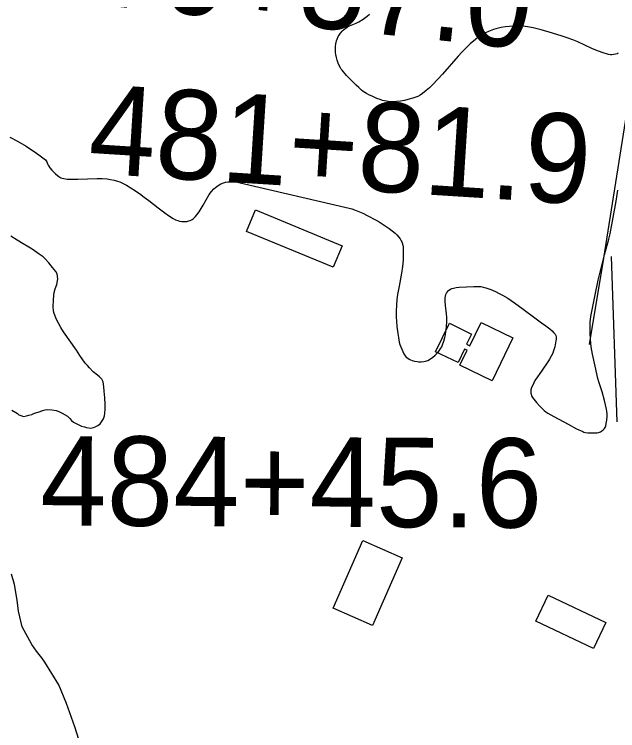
# Model space of a CAD drawing. Extents: x 3161615 to 3199515, y 867541 to 892976.
# Drawn here: x 3176440 to 3177115, y 880727 to 881529 of the extents above; entities that cross this region are included whole.
import ezdxf

# ---------------------------------------------------------------- set-up
doc = ezdxf.new("R2010")
doc.units = 0
for name, color, linetype in [('V-BLDG-OTLN', 7, 'Continuous'), ('V-SITE-VEGE', 7, 'Continuous'), ('V-SURV-IDEN', 7, 'Continuous'), ('V-TOPO-SHOR', 7, 'Continuous')]:
    doc.layers.add(name, color=color, linetype=linetype)

msp = doc.modelspace()

# ---------------------------------------------------------------- linework, layer by layer
at = {"layer": 'V-BLDG-OTLN'}
for points in [[(3176709.39, 881309.68), (3176806.32, 881269.65), (3176796.36, 881245.54), (3176699.43, 881285.56)], [(3176974.18, 881118.57), (3176938.19, 881136.05), (3176946.24, 881152.63), (3176943.37, 881154.03), (3176935.99, 881138.84), (3176910.95, 881151.01), (3176926.39, 881182.79), (3176951.12, 881170.77), (3176945.62, 881159.45), (3176949.1, 881157.76), (3176961.72, 881183.73), (3176997.41, 881166.4)], [(3176796.44, 880864.16), (3176829.6, 880939.81), (3176873.59, 880920.53), (3176840.43, 880844.87)], [(3177022.88, 880849.66), (3177036.62, 880878.78), (3177101.37, 880848.23), (3177087.63, 880819.11)]]:
    msp.add_lwpolyline(points, close=True, dxfattribs=at)
at = {"layer": 'V-SITE-VEGE'}
for p, q in [((3176825.15, 881520.24), (3176829.77, 881523.17)), ((3176829.77, 881523.17), (3176834.24, 881526.3)), ((3176834.24, 881526.3), (3176837.12, 881528.54)), ((3176812.12, 881514.2), (3176814.51, 881515.5)), ((3176814.51, 881515.5), (3176821.96, 881518.6)), ((3176821.96, 881518.6), (3176825.15, 881520.24)), ((3176988.92, 881514.53), (3176984.22, 881513.8)), ((3176993.63, 881514.98), (3176988.92, 881514.53)), ((3177002.49, 881515.43), (3176993.63, 881514.98)), ((3177008.19, 881515.32), (3177002.49, 881515.43)), ((3177011.03, 881515.08), (3177008.19, 881515.32)), ((3177013.85, 881514.68), (3177011.03, 881515.08)), ((3177019.95, 881513.49), (3177013.85, 881514.68)), ((3176802.94, 881505.16), (3176804.57, 881507.52)), ((3176804.57, 881507.52), (3176806.36, 881509.6)), ((3176806.36, 881509.6), (3176807.64, 881510.85)), ((3176807.64, 881510.85), (3176809.46, 881512.37)), ((3176809.46, 881512.37), (3176812.12, 881514.2)), ((3176966.73, 881507.75), (3176962.27, 881505.26)), ((3176970.23, 881509.41), (3176966.73, 881507.75)), ((3176975.57, 881511.5), (3176970.23, 881509.41)), ((3176978.3, 881512.38), (3176975.57, 881511.5)), ((3176981.1, 881513.12), (3176978.3, 881512.38)), ((3176984.22, 881513.8), (3176981.1, 881513.12)), ((3177028.98, 881511.28), (3177019.95, 881513.49)), ((3177037.93, 881508.7), (3177028.98, 881511.28)), ((3177051.33, 881504.54), (3177037.93, 881508.7)), ((3176799.48, 881495.64), (3176800.17, 881498.8)), ((3176800.17, 881498.8), (3176800.84, 881500.88)), ((3176800.84, 881500.88), (3176802.06, 881503.61)), ((3176802.06, 881503.61), (3176802.94, 881505.16)), ((3176955.38, 881500.38), (3176949.64, 881495.51)), ((3176958.07, 881502.44), (3176955.38, 881500.38)), ((3176962.27, 881505.26), (3176958.07, 881502.44)), ((3177057.95, 881502.31), (3177051.33, 881504.54)), ((3177064.52, 881499.88), (3177057.95, 881502.31)), ((3177069.85, 881497.62), (3177064.52, 881499.88)), ((3176798.99, 881488.61), (3176799.12, 881492.45)), ((3176799.12, 881492.45), (3176799.48, 881495.64)), ((3176949.64, 881495.51), (3176944.19, 881490.33)), ((3177085.6, 881490.22), (3177069.85, 881497.62)), ((3176799.11, 881485.71), (3176798.99, 881488.61)), ((3176799.33, 881483.54), (3176799.11, 881485.71)), ((3176799.91, 881480.28), (3176799.33, 881483.54)), ((3176940.7, 881486.74), (3176936.17, 881481.84)), ((3176944.19, 881490.33), (3176940.7, 881486.74)), ((3177090.21, 881488.32), (3177085.6, 881490.22)), ((3177097.23, 881485.76), (3177090.21, 881488.32)), ((3177104.33, 881483.56), (3177097.23, 881485.76)), ((3177106.33, 881483.23), (3177104.33, 881483.56)), ((3177107.87, 881483.23), (3177106.33, 881483.23)), ((3177110.2, 881483.49), (3177107.87, 881483.23)), ((3177113.9, 881484.24), (3177110.2, 881483.49)), ((3177114.52, 881484.56), (3177113.9, 881484.24)), ((3177115.02, 881485.09), (3177114.52, 881484.56)), ((3176800.81, 881477.08), (3176799.91, 881480.28)), ((3176801.91, 881474.07), (3176800.81, 881477.08)), ((3176936.17, 881481.84), (3176918.61, 881461.63)), ((3176802.83, 881471.9), (3176801.91, 881474.07)), ((3176804.47, 881468.79), (3176802.83, 881471.9)), ((3176805.43, 881467.31), (3176804.47, 881468.79)), ((3176806.51, 881465.89), (3176805.43, 881467.31)), ((3176811.43, 881460.25), (3176806.51, 881465.89)), ((3176816.56, 881454.87), (3176811.43, 881460.25)), ((3176918.61, 881461.63), (3176913.47, 881455.95)), ((3176822.19, 881449.24), (3176816.56, 881454.87)), ((3176913.47, 881455.95), (3176907.38, 881449.69)), ((3176825.09, 881446.51), (3176822.19, 881449.24)), ((3176828.11, 881443.86), (3176825.09, 881446.51)), ((3176830.01, 881442.35), (3176828.11, 881443.86)), ((3176833.51, 881440.03), (3176830.01, 881442.35)), ((3176900.28, 881443.16), (3176896.14, 881439.79)), ((3176904, 881446.47), (3176900.28, 881443.16)), ((3176907.38, 881449.69), (3176904, 881446.47)), ((3176836.25, 881438.49), (3176833.51, 881440.03)), ((3176840.54, 881436.43), (3176836.25, 881438.49)), ((3176845, 881434.52), (3176840.54, 881436.43)), ((3176848.76, 881433.1), (3176845, 881434.52)), ((3176885.47, 881434.73), (3176879.89, 881433.13)), ((3176890.96, 881436.77), (3176885.47, 881434.73)), ((3176893.66, 881438.11), (3176890.96, 881436.77)), ((3176896.14, 881439.79), (3176893.66, 881438.11)), ((3176851.6, 881432.21), (3176848.76, 881433.1)), ((3176855.89, 881431.22), (3176851.6, 881432.21)), ((3176858.04, 881430.9), (3176855.89, 881431.22)), ((3176860.22, 881430.7), (3176858.04, 881430.9)), ((3176864.18, 881430.65), (3176860.22, 881430.7)), ((3176867.16, 881430.83), (3176864.18, 881430.65)), ((3176871.64, 881431.38), (3176867.16, 881430.83)), ((3176876.09, 881432.23), (3176871.64, 881431.38)), ((3176879.89, 881433.13), (3176876.09, 881432.23)), ((3176434.91, 881391.12), (3176443.41, 881386.54)), ((3176443.41, 881386.54), (3176452.95, 881380.92)), ((3176452.95, 881380.92), (3176457.96, 881377.72)), ((3176457.96, 881377.72), (3176463.23, 881374.15)), ((3176463.23, 881374.15), (3176468.76, 881370.13)), ((3176468.76, 881370.13), (3176474.56, 881365.59)), ((3176474.56, 881365.59), (3176475.4, 881364.65)), ((3176475.4, 881364.65), (3176475.97, 881363.53)), ((3176475.97, 881363.53), (3176476.83, 881361.09)), ((3176476.83, 881361.09), (3176477.58, 881359.58)), ((3176477.58, 881359.58), (3176479.6, 881356.74)), ((3176479.6, 881356.74), (3176481.8, 881354)), ((3176481.8, 881354), (3176483.44, 881352.23)), ((3176483.44, 881352.23), (3176485.66, 881350.07)), ((3176485.66, 881350.07), (3176487.98, 881348.07)), ((3176487.98, 881348.07), (3176489.61, 881346.9)), ((3176489.61, 881346.9), (3176491.91, 881345.65)), ((3176491.91, 881345.65), (3176493.31, 881345.13)), ((3176493.31, 881345.13), (3176494.98, 881344.73)), ((3176494.98, 881344.73), (3176498.91, 881344.26)), ((3176498.91, 881344.26), (3176502.84, 881344.06)), ((3176502.84, 881344.06), (3176510.7, 881344.09)), ((3176510.7, 881344.09), (3176532.59, 881344.79)), ((3176532.59, 881344.79), (3176538.17, 881344.71)), ((3176538.17, 881344.71), (3176543.75, 881344.29)), ((3176543.75, 881344.29), (3176547.47, 881343.81)), ((3176547.47, 881343.81), (3176551.35, 881343.05)), ((3176551.35, 881343.05), (3176555.15, 881341.97)), ((3176555.15, 881341.97), (3176557.62, 881341.08)), ((3176557.62, 881341.08), (3176560.86, 881339.69)), ((3176560.86, 881339.69), (3176565.03, 881337.48)), ((3176667.82, 881337.14), (3176670.75, 881338.85)), ((3176670.75, 881338.85), (3176673.76, 881340.1)), ((3176673.76, 881340.1), (3176675.8, 881340.67)), ((3176675.8, 881340.67), (3176678.58, 881341.1)), ((3176678.58, 881341.1), (3176680.18, 881341.17)), ((3176680.18, 881341.17), (3176684.71, 881341.06)), ((3176684.71, 881341.06), (3176689.24, 881340.59)), ((3176689.24, 881340.59), (3176692.21, 881340.02)), ((3176692.21, 881340.02), (3176814.27, 881311.63)), ((3176565.03, 881337.48), (3176572.42, 881332.84)), ((3176572.42, 881332.84), (3176579.58, 881327.98)), ((3176657.8, 881326.93), (3176660.14, 881330.17)), ((3176660.14, 881330.17), (3176662.8, 881333.1)), ((3176662.8, 881333.1), (3176664.8, 881334.9)), ((3176664.8, 881334.9), (3176667.82, 881337.14)), ((3177112.73, 881319.45), (3177114.73, 881331.65)), ((3176579.58, 881327.98), (3176585.02, 881324.11)), ((3176585.02, 881324.11), (3176590.3, 881320.12)), ((3176650.8, 881314.89), (3176657.8, 881326.93)), ((3176590.3, 881320.12), (3176600.76, 881311.97)), ((3176646.44, 881307.63), (3176650.8, 881314.89)), ((3177109.52, 881301.2), (3177112.73, 881319.45)), ((3176600.76, 881311.97), (3176607.92, 881306.56)), ((3176607.92, 881306.56), (3176612.17, 881303.52)), ((3176643.95, 881304.11), (3176646.44, 881307.63)), ((3176814.27, 881311.63), (3176817.22, 881310.85)), ((3176817.22, 881310.85), (3176820.11, 881309.91)), ((3176820.11, 881309.91), (3176825.78, 881307.65)), ((3176825.78, 881307.65), (3176829.48, 881305.94)), ((3176612.17, 881303.52), (3176617.23, 881300.13)), ((3176617.23, 881300.13), (3176619.85, 881298.72)), ((3176619.85, 881298.72), (3176622.6, 881297.7)), ((3176636.52, 881297.86), (3176638.51, 881298.89)), ((3176638.51, 881298.89), (3176639.61, 881299.65)), ((3176639.61, 881299.65), (3176640.8, 881300.67)), ((3176640.8, 881300.67), (3176642.47, 881302.38)), ((3176642.47, 881302.38), (3176643.95, 881304.11)), ((3176829.48, 881305.94), (3176834.37, 881303.5)), ((3176834.37, 881303.5), (3176844.43, 881298.23)), ((3176844.43, 881298.23), (3176847.89, 881296.21)), ((3177105.97, 881283), (3177109.52, 881301.2)), ((3176622.6, 881297.7), (3176624.47, 881297.22)), ((3176624.47, 881297.22), (3176626.98, 881296.82)), ((3176626.98, 881296.82), (3176630.27, 881296.64)), ((3176630.27, 881296.64), (3176632.62, 881296.8)), ((3176632.62, 881296.8), (3176634.97, 881297.3)), ((3176634.97, 881297.3), (3176636.52, 881297.86)), ((3176847.89, 881296.21), (3176854.65, 881291.89)), ((3176854.65, 881291.89), (3176859.1, 881288.8)), ((3176859.1, 881288.8), (3176862.43, 881286.36)), ((3176862.43, 881286.36), (3176865.57, 881283.77)), ((3176865.57, 881283.77), (3176867.52, 881281.9)), ((3177104.57, 881277.02), (3177105.97, 881283)), ((3176442.76, 881275.83), (3176435.72, 881280.27)), ((3176449.67, 881271.85), (3176442.76, 881275.83)), ((3176867.52, 881281.9), (3176869.93, 881279.15)), ((3176869.93, 881279.15), (3176871.18, 881277.42)), ((3176871.18, 881277.42), (3176872.49, 881275.28)), ((3176872.49, 881275.28), (3176873.13, 881274)), ((3176873.13, 881274), (3176873.62, 881272.71)), ((3177099.66, 881259.25), (3177104.57, 881277.02)), ((3176455.89, 881267.88), (3176449.67, 881271.85)), ((3176459.64, 881265.66), (3176455.89, 881267.88)), ((3176873.62, 881272.71), (3176874.28, 881270.09)), ((3176874.28, 881270.09), (3176874.52, 881268.31)), ((3176874.52, 881268.31), (3176874.68, 881265.93)), ((3176874.68, 881265.93), (3176874.79, 881259.73)), ((3176467.62, 881260.17), (3176459.64, 881265.66)), ((3176471.84, 881257.01), (3176467.62, 881260.17)), ((3176874.79, 881259.73), (3176874.53, 881253.56)), ((3177095.7, 881243.08), (3177099.66, 881259.25)), ((3176474.07, 881255.03), (3176471.84, 881257.01)), ((3176478.17, 881250.46), (3176474.07, 881255.03)), ((3176482.51, 881245.43), (3176478.17, 881250.46)), ((3176874.53, 881253.56), (3176873.74, 881246.3)), ((3176486.03, 881240.75), (3176482.51, 881245.43)), ((3176873.74, 881246.3), (3176872.65, 881239.05)), ((3177092.87, 881230.93), (3177095.7, 881243.08)), ((3176487.56, 881238.18), (3176486.03, 881240.75)), ((3176488.39, 881232.56), (3176487.56, 881238.18)), ((3176872.65, 881239.05), (3176870.06, 881224.56)), ((3176485.6, 881221.54), (3176487.23, 881226.35)), ((3176487.23, 881226.35), (3176488.39, 881232.56)), ((3177088.87, 881212.64), (3177092.87, 881230.93)), ((3176484.43, 881217.21), (3176485.6, 881221.54)), ((3176870.06, 881224.56), (3176868.44, 881214.91)), ((3176922.99, 881216.39), (3176924.06, 881218.03)), ((3176924.06, 881218.03), (3176924.89, 881218.98)), ((3176924.89, 881218.98), (3176925.76, 881219.79)), ((3176925.76, 881219.79), (3176927.63, 881221.06)), ((3176927.63, 881221.06), (3176928.98, 881221.66)), ((3176928.98, 881221.66), (3176930.91, 881222.22)), ((3176930.91, 881222.22), (3176933.99, 881222.79)), ((3176933.99, 881222.79), (3176937.08, 881223.17)), ((3176937.08, 881223.17), (3176953.51, 881224.15)), ((3176953.51, 881224.15), (3176956.92, 881224.17)), ((3176956.92, 881224.17), (3176961.47, 881223.85)), ((3176961.47, 881223.85), (3176964.06, 881223.41)), ((3176964.06, 881223.41), (3176967.01, 881222.61)), ((3176967.01, 881222.61), (3176972.58, 881220.6)), ((3176972.58, 881220.6), (3176977.93, 881218.3)), ((3176977.93, 881218.3), (3176981.39, 881216.62)), ((3176483.51, 881208.42), (3176484.08, 881214.86)), ((3176484.08, 881214.86), (3176484.43, 881217.21)), ((3176868.44, 881214.91), (3176867.69, 881209.39)), ((3176921.68, 881207.92), (3176921.73, 881211.18)), ((3176921.73, 881211.18), (3176921.94, 881213.18)), ((3176921.94, 881213.18), (3176922.45, 881215.12)), ((3176922.45, 881215.12), (3176922.99, 881216.39)), ((3176981.39, 881216.62), (3176985.88, 881214.22)), ((3176985.88, 881214.22), (3176991.69, 881210.77)), ((3176991.69, 881210.77), (3176999.2, 881205.79)), ((3177085.22, 881194.22), (3177088.87, 881212.64)), ((3176483.04, 881203.85), (3176483.39, 881206.08)), ((3176483.17, 881200.45), (3176483.04, 881203.85)), ((3176483.39, 881206.08), (3176483.51, 881208.42)), ((3176867.09, 881203.07), (3176866.79, 881196.43)), ((3176867.69, 881209.39), (3176867.09, 881203.07)), ((3176922.08, 881202.22), (3176921.68, 881207.92)), ((3176923.09, 881193.66), (3176922.08, 881202.22)), ((3176999.2, 881205.79), (3177008.94, 881198.69)), ((3176483.41, 881197.64), (3176483.17, 881200.45)), ((3176483.88, 881195.07), (3176483.41, 881197.64)), ((3176486.7, 881187.69), (3176483.88, 881195.07)), ((3176866.79, 881196.43), (3176866.82, 881189.77)), ((3177008.94, 881198.69), (3177021.86, 881188.85)), ((3177084.62, 881190.57), (3177085.22, 881194.22)), ((3176491.87, 881178.09), (3176486.7, 881187.69)), ((3176866.82, 881189.77), (3176867.02, 881185.31)), ((3176923.43, 881189.38), (3176923.09, 881193.66)), ((3176923.44, 881185.11), (3176923.43, 881189.38)), ((3177021.86, 881188.85), (3177029.41, 881183.27)), ((3177083.9, 881184.14), (3177084.62, 881190.57)), ((3176494.93, 881173.3), (3176491.87, 881178.09)), ((3176867.02, 881185.31), (3176867.51, 881179.37)), ((3176867.51, 881179.37), (3176868.52, 881171.45)), ((3176922.44, 881173.48), (3176923, 881178.45)), ((3176923, 881178.45), (3176923.44, 881185.11)), ((3177029.41, 881183.27), (3177034.09, 881180.07)), ((3177034.09, 881180.07), (3177038.59, 881176.82)), ((3177083.63, 881179.29), (3177083.9, 881184.14)), ((3177083.64, 881172.03), (3177083.63, 881179.29)), ((3176509.13, 881152.7), (3176494.93, 881173.3)), ((3176868.52, 881171.45), (3176869.29, 881166.94)), ((3176921.25, 881167), (3176921.83, 881169.77)), ((3176921.83, 881169.77), (3176922.44, 881173.48)), ((3177038.59, 881176.82), (3177041.38, 881174.32)), ((3177041.38, 881174.32), (3177042.88, 881172.69)), ((3177042.88, 881172.69), (3177044.47, 881170.59)), ((3177044.47, 881170.59), (3177045.25, 881169.09)), ((3177084.09, 881164.8), (3177083.64, 881172.03)), ((3176869.29, 881166.94), (3176870.33, 881161.79)), ((3176870.33, 881161.79), (3176871.05, 881159.03)), ((3176918.63, 881158.69), (3176920.11, 881162.84)), ((3176920.11, 881162.84), (3176921.25, 881167)), ((3177045.48, 881163.07), (3177044.09, 881156.31)), ((3177045.25, 881169.09), (3177045.66, 881167.52)), ((3177045.73, 881165), (3177045.48, 881163.07)), ((3177045.66, 881167.52), (3177045.76, 881166.45)), ((3177045.76, 881166.45), (3177045.73, 881165)), ((3177085.04, 881156.5), (3177084.09, 881164.8)), ((3176871.05, 881159.03), (3176871.96, 881156.35)), ((3176871.96, 881156.35), (3176874.19, 881151.1)), ((3176914.85, 881152.05), (3176916.74, 881154.85)), ((3176916.74, 881154.85), (3176917.69, 881156.58)), ((3176917.69, 881156.58), (3176918.63, 881158.69)), ((3177044.09, 881156.31), (3177042.92, 881152.1)), ((3177085.68, 881152.37), (3177085.04, 881156.5)), ((3176513, 881146.74), (3176509.13, 881152.7)), ((3176519.11, 881138.08), (3176513, 881146.74)), ((3176874.19, 881151.1), (3176875.39, 881148.72)), ((3176875.39, 881148.72), (3176876.85, 881146.51)), ((3176876.85, 881146.51), (3176878.04, 881145.09)), ((3176907.46, 881144.63), (3176910.52, 881147.32)), ((3176910.52, 881147.32), (3176913.23, 881150.1)), ((3176913.23, 881150.1), (3176914.85, 881152.05)), ((3177040.22, 881145.98), (3177038.47, 881142.74)), ((3177041.83, 881149.35), (3177040.22, 881145.98)), ((3177042.92, 881152.1), (3177041.83, 881149.35)), ((3177086.46, 881148.26), (3177085.68, 881152.37)), ((3177089.32, 881134.89), (3177086.46, 881148.26)), ((3176521.46, 881135.5), (3176519.11, 881138.08)), ((3176878.04, 881145.09), (3176879.69, 881143.63)), ((3176879.69, 881143.63), (3176881.5, 881142.51)), ((3176881.5, 881142.51), (3176882.78, 881141.92)), ((3176882.78, 881141.92), (3176884.57, 881141.26)), ((3176884.57, 881141.26), (3176887.32, 881140.49)), ((3176887.32, 881140.49), (3176890.15, 881140)), ((3176890.15, 881140), (3176892.06, 881139.84)), ((3176892.06, 881139.84), (3176894.59, 881139.83)), ((3176894.59, 881139.83), (3176897.92, 881140.2)), ((3176897.92, 881140.2), (3176899.78, 881140.61)), ((3176899.78, 881140.61), (3176902.06, 881141.37)), ((3176902.06, 881141.37), (3176904.23, 881142.41)), ((3176904.23, 881142.41), (3176905.64, 881143.27)), ((3176905.64, 881143.27), (3176907.46, 881144.63)), ((3177037.17, 881140.66), (3177029.5, 881129.45)), ((3177038.47, 881142.74), (3177037.17, 881140.66)), ((3176523.8, 881133.17), (3176521.46, 881135.5)), ((3176527.79, 881128.6), (3176523.8, 881133.17)), ((3177092.52, 881121.02), (3177089.32, 881134.89)), ((3176532.95, 881124.86), (3176527.79, 881128.6)), ((3176535.06, 881122.87), (3176532.95, 881124.86)), ((3176537.64, 881120.18), (3176535.06, 881122.87)), ((3177029.5, 881129.45), (3177022.99, 881120.41)), ((3176539.05, 881117.26), (3176537.64, 881120.18)), ((3176539.88, 881111.87), (3176539.05, 881117.26)), ((3177019.49, 881113.72), (3177018.34, 881110.99)), ((3177022, 881118.81), (3177019.49, 881113.72)), ((3177022.99, 881120.41), (3177022, 881118.81)), ((3177093.58, 881117.23), (3177092.52, 881121.02)), ((3177097.22, 881105.98), (3177093.58, 881117.23)), ((3176540.12, 881107.07), (3176539.88, 881111.87)), ((3176540.96, 881099.46), (3176540.12, 881107.07)), ((3177017.49, 881108.2), (3177017.3, 881106.44)), ((3177017.3, 881106.44), (3177017.47, 881104.62)), ((3177018.34, 881110.99), (3177017.49, 881108.2)), ((3177099.83, 881096.32), (3177097.22, 881105.98)), ((3176541.32, 881092.31), (3176540.96, 881099.46)), ((3177017.47, 881104.62), (3177017.77, 881103.42)), ((3177017.77, 881103.42), (3177018.34, 881101.85)), ((3177018.34, 881101.85), (3177019.38, 881099.84)), ((3177019.38, 881099.84), (3177020.69, 881098.01)), ((3177020.69, 881098.01), (3177023.82, 881094.18)), ((3176541.33, 881086.69), (3176541.32, 881092.31)), ((3177023.82, 881094.18), (3177027, 881090.46)), ((3177027, 881090.46), (3177029.21, 881088.12)), ((3177102.1, 881086.61), (3177099.83, 881096.32)), ((3176436.96, 881085.59), (3176441.42, 881083.14)), ((3176441.42, 881083.14), (3176443.29, 881081.85)), ((3176443.29, 881081.85), (3176444.93, 881080.56)), ((3176459.46, 881080.94), (3176462.27, 881082.11)), ((3176462.27, 881082.11), (3176466.37, 881083.53)), ((3176466.37, 881083.53), (3176471.75, 881085.29)), ((3176471.75, 881085.29), (3176474.21, 881086)), ((3176474.21, 881086), (3176476.9, 881086.35)), ((3176476.9, 881086.35), (3176481.82, 881086.13)), ((3176481.82, 881086.13), (3176486.63, 881085.2)), ((3176486.63, 881085.2), (3176489.56, 881084.15)), ((3176489.56, 881084.15), (3176493.19, 881082.28)), ((3176493.19, 881082.28), (3176499.05, 881078.77)), ((3176540.63, 881079.43), (3176540.98, 881082.12)), ((3176540.98, 881082.12), (3176541.33, 881086.69)), ((3177029.21, 881088.12), (3177032.34, 881085.22)), ((3177032.34, 881085.22), (3177034.25, 881083.72)), ((3177034.25, 881083.72), (3177036.59, 881082.16)), ((3177036.59, 881082.16), (3177042.99, 881078.49)), ((3177102.47, 881084.64), (3177102.1, 881086.61)), ((3177102.79, 881081.15), (3177102.47, 881084.64)), ((3176444.93, 881080.56), (3176447.04, 881079.51)), ((3176447.04, 881079.51), (3176449.85, 881078.47)), ((3176449.85, 881078.47), (3176453.49, 881079.41)), ((3176453.49, 881079.41), (3176455.83, 881079.88)), ((3176455.83, 881079.88), (3176459.46, 881080.94)), ((3176499.05, 881078.77), (3176501.98, 881076.32)), ((3176501.98, 881076.32), (3176503.86, 881074.21)), ((3176503.86, 881074.21), (3176505.86, 881072.34)), ((3176535.73, 881070.52), (3176539.59, 881075.79)), ((3176539.59, 881075.79), (3176540.63, 881079.43)), ((3177042.99, 881078.49), (3177059, 881069.84)), ((3177101.79, 881070.56), (3177102.46, 881074.51)), ((3177102.46, 881074.51), (3177102.8, 881078.5)), ((3177102.8, 881078.5), (3177102.79, 881081.15)), ((3176505.86, 881072.34), (3176511.13, 881069.54)), ((3176511.13, 881069.54), (3176514.77, 881067.91)), ((3176514.77, 881067.91), (3176518.17, 881066.86)), ((3176518.17, 881066.86), (3176520.63, 881066.16)), ((3176520.63, 881066.16), (3176525.19, 881065.46)), ((3176525.19, 881065.46), (3176528.12, 881066.17)), ((3176528.12, 881066.17), (3176530.11, 881066.88)), ((3176530.11, 881066.88), (3176533.04, 881068.4)), ((3176533.04, 881068.4), (3176535.73, 881070.52)), ((3177059, 881069.84), (3177068.65, 881064.84)), ((3177099.67, 881065.15), (3177100.39, 881066.37)), ((3177100.39, 881066.37), (3177101.12, 881068.11)), ((3177101.12, 881068.11), (3177101.79, 881070.56)), ((3177068.65, 881064.84), (3177075.4, 881061.66)), ((3177075.4, 881061.66), (3177076.81, 881061.12)), ((3177076.81, 881061.12), (3177078.25, 881060.76)), ((3177078.25, 881060.76), (3177081.19, 881060.39)), ((3177081.19, 881060.39), (3177089.41, 881060.31)), ((3177089.41, 881060.31), (3177091.72, 881060.42)), ((3177091.72, 881060.42), (3177093.26, 881060.69)), ((3177093.26, 881060.69), (3177095.3, 881061.39)), ((3177095.3, 881061.39), (3177096.45, 881062.03)), ((3177096.45, 881062.03), (3177098.28, 881063.47)), ((3177098.28, 881063.47), (3177099.67, 881065.15)), ((3176439.77, 880890.72), (3176436.46, 880902.17)), ((3176443.05, 880872.89), (3176439.77, 880890.72)), ((3176444.34, 880860.78), (3176443.05, 880872.89)), ((3176448.63, 880843.27), (3176444.34, 880860.78)), ((3176459.29, 880823.38), (3176448.63, 880843.27)), ((3176464.64, 880815.96), (3176459.29, 880823.38)), ((3176470.66, 880808.53), (3176464.64, 880815.96)), ((3176474, 880803.81), (3176470.66, 880808.53)), ((3176489.35, 880778.18), (3176474, 880803.81)), ((3176497.99, 880757.29), (3176489.35, 880778.18)), ((3176507.28, 880731.36), (3176497.99, 880757.29)), ((3176514.25, 880710.14), (3176507.28, 880731.36))]:
    msp.add_line(p, q, dxfattribs=at)
at = {"layer": 'V-TOPO-SHOR'}
msp.add_line((3177114.14, 881072.64), (3177107.6, 881257.63), dxfattribs=at)
msp.add_lwpolyline([(3177263.56, 882233.16), (3177200.87, 881858.1), (3177166.82, 881650.32), (3177125.68, 881424.94), (3177098.79, 881255.89), (3177082.67, 881159.05)], dxfattribs=at)

# ---------------------------------------------------------------- texts
at = {"layer": 'V-SURV-IDEN'}
for s, rotation, p in [('479+57.0', 354.0525, (3176455.68, 881547.3)), ('481+81.9', 356.38169, (3176521.15, 881350.94)), ('484+45.6', 359.72408, (3176468.46, 880956.76))]:
    msp.add_text(s, height=100, rotation=rotation, dxfattribs=at).set_placement(p)

doc.saveas('drawing.dxf')
